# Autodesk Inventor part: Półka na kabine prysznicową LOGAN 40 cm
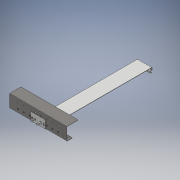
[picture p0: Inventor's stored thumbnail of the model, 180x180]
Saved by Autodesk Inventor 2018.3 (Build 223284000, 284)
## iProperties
Created: 2021-05
Part Number: Półka na kabine prysznicową LOGAN 40 cm
Material: Ogólny
Document SubType Name: Modeling
Designer: Verical
Density: 1 g/cm^3
Appearance: Domyślna
Author: Verical
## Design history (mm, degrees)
derived "Półka na kabine prysznicową LOGAN.iam"
node "Bryła1"
node "Uchwyt na Docie.ipt:1"
node "Odbojnik.ipt:1"
node "Odbojnik.ipt:2"
node "Śruba motylkowa.ipt:1"
node "Śruba motylkowa.ipt:2"
node "Śruba imbusowa.ipt:1"
node "Śruba imbusowa.ipt:2"
node "Półka prysznicowa - 40 cm.ipt:1"
node "Odbojnik większy.ipt:3"
node "Odbojnik większy.ipt:4"
